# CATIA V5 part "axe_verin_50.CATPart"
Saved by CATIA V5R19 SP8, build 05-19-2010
Part number: axe_verin_50
Bounding box of the stored display mesh (mm): x -16 to 16, y -16 to 16, z -115 to 30
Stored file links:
  C:\Users\ThinkMotion\Desktop\EU_thinkMotion\iao\IAO_MMS_Groupe3\avercruysse\IAO_vercruysse\IAO_vercruysse\axe_verin_50.CATPart
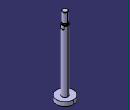
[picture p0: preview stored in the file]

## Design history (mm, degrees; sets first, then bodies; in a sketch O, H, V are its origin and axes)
Body1 "1" (main body)
  Solid1 "3": solid without history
